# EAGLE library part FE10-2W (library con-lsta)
FEMALE HEADER
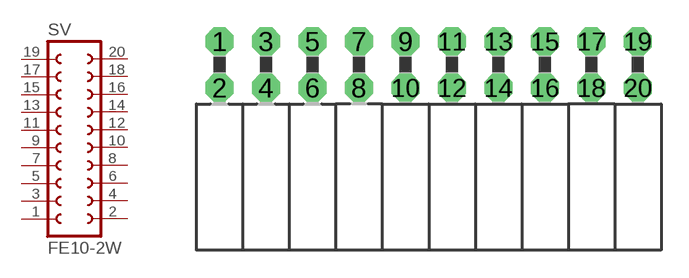
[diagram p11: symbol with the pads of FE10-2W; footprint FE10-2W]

Designator prefix SV

## FE10-2W (OC_FARNELL: unknown; OC_NEWARK: unknown)  [FE10-2W]
1  1  pas
2  2  pas
3  3  pas
4  4  pas
5  5  pas
6  6  pas
7  7  pas
8  8  pas
9  9  pas
10  10  pas
11  11  pas
12  12  pas
13  13  pas
14  14  pas
15  15  pas
16  16  pas
17  17  pas
18  18  pas
19  19  pas
20  20  pas

## Footprint FE10-2W (pad centres in mm)
FEMALE HEADER
drill 1.016 octagon: 1 -11.43,1.27; 2 -11.43,-1.27; 3 -8.89,1.27; 4 -8.89,-1.27; 5 -6.35,1.27; 6 -6.35,-1.27; 7 -3.81,1.27; 8 -3.81,-1.27; 9 -1.27,1.27; 10 -1.27,-1.27; 11 1.27,1.27; 12 1.27,-1.27; 13 3.81,1.27; 14 3.81,-1.27; 15 6.35,1.27; 16 6.35,-1.27; 17 8.89,1.27; 18 8.89,-1.27; 19 11.43,1.27; 20 11.43,-1.27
